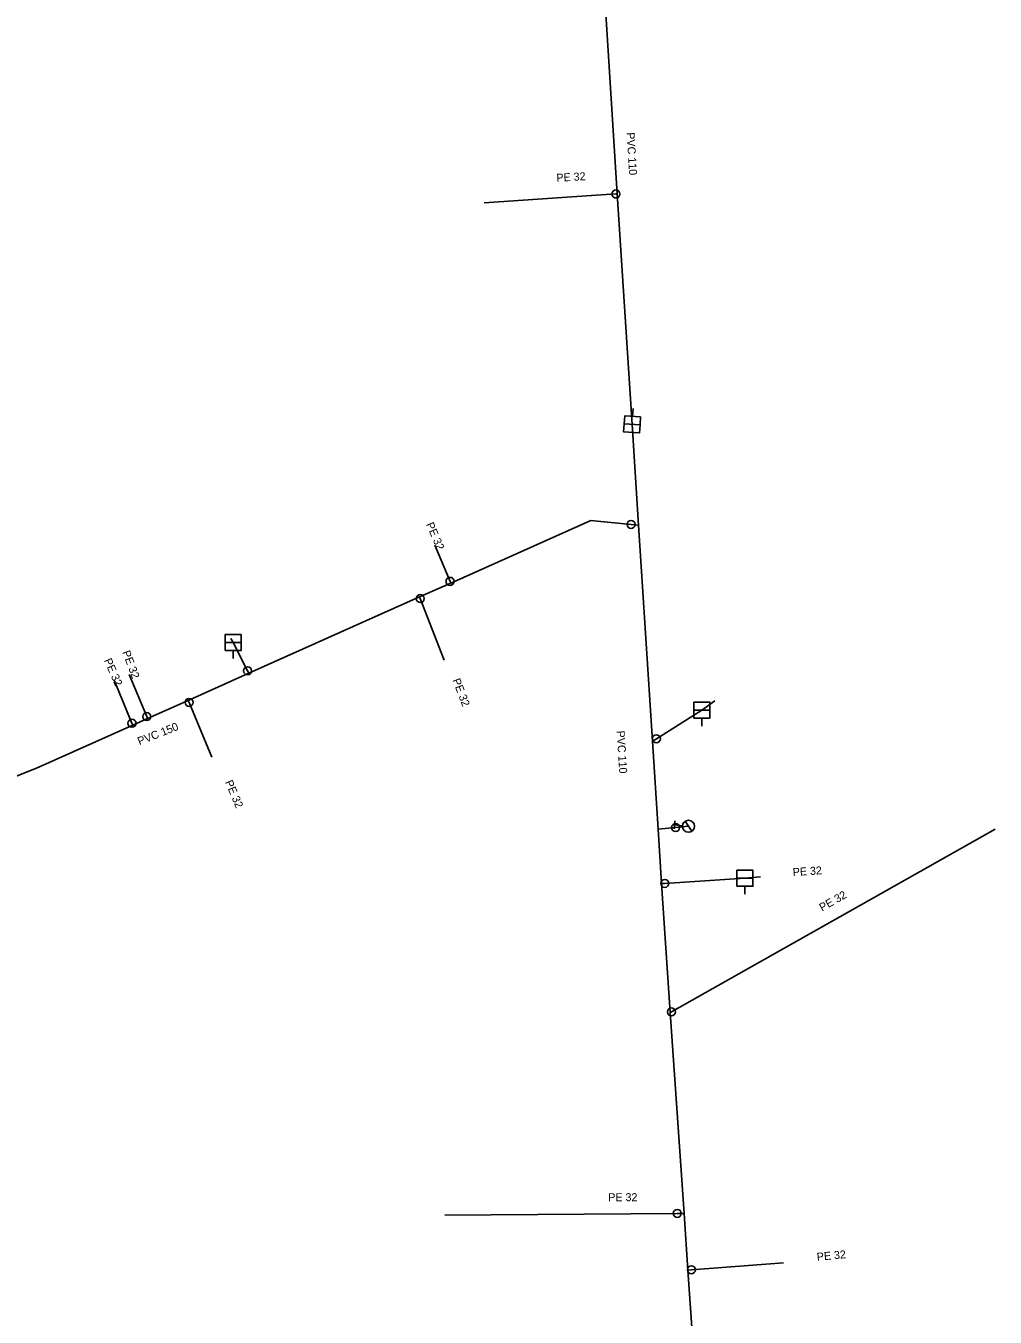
# Model space of a CAD drawing. Extents: x -725126 to -724740, y -1049524 to -1048684.
# Drawn here: x -724993.9 to -724872.7, y -1049098.7 to -1048937.4 of the extents above; entities that cross this region are included whole.
import ezdxf

# ---------------------------------------------------------------- set-up
doc = ezdxf.new("R2010")
doc.units = 0
doc.layers.add('Level 0', color=7, linetype='Continuous')

msp = doc.modelspace()

# ---------------------------------------------------------------- linework, layer by layer
at = {"layer": 'Level 0'}
for p, q in [((-724921.5, -1048934.52), (-724919.97, -1048958.36)), ((-724936.63, -1048959.48), (-724920.14, -1048958.37)), ((-724920.14, -1048958.37), (-724919.97, -1048958.36)), ((-724919.97, -1048958.36), (-724918.12, -1048987.16)), ((-724917.99, -1048985.16), (-724918.06, -1048986.16)), ((-724918.12, -1048987.16), (-724917.32, -1048999.76)), ((-724923.28, -1048999.16), (-724940.79, -1049006.98)), ((-724918.25, -1048999.66), (-724923.28, -1048999.16)), ((-724917.3, -1048999.75), (-724918.25, -1048999.66)), ((-724917.32, -1048999.76), (-724917.3, -1048999.75)), ((-724917.32, -1048999.76), (-724915.59, -1049026.75)), ((-724942.79, -1049002.23), (-724940.88, -1049006.77)), ((-724940.79, -1049006.98), (-724944.68, -1049008.72)), ((-724940.88, -1049006.77), (-724940.79, -1049006.98)), ((-724944.68, -1049008.72), (-724966.04, -1049018.25)), ((-724944.6, -1049008.93), (-724944.68, -1049008.72)), ((-724941.63, -1049016.62), (-724944.6, -1049008.93)), ((-724968.26, -1049013.9), (-724967.99, -1049014.42)), ((-724967.99, -1049014.42), (-724966.19, -1049017.95)), ((-724967.99, -1049016.42), (-724967.99, -1049015.42)), ((-724966.19, -1049017.95), (-724966.04, -1049018.25)), ((-724982.86, -1049019.12), (-724980.63, -1049024.5)), ((-724980.99, -1049018.4), (-724978.79, -1049023.67)), ((-724966.04, -1049018.25), (-724973.61, -1049021.64)), ((-724973.61, -1049021.64), (-724978.7, -1049023.91)), ((-724973.5, -1049021.9), (-724973.61, -1049021.64)), ((-724970.64, -1049028.72), (-724973.5, -1049021.9)), ((-724909.4, -1049022.86), (-724915.09, -1049026.44)), ((-724907.79, -1049021.68), (-724909.4, -1049022.86)), ((-724978.7, -1049023.91), (-724980.53, -1049024.73)), ((-724978.79, -1049023.67), (-724978.7, -1049023.91)), ((-724909.4, -1049024.86), (-724909.4, -1049023.86)), ((-724980.53, -1049024.73), (-724992.57, -1049030.1)), ((-724980.63, -1049024.5), (-724980.53, -1049024.73)), ((-724915.09, -1049026.44), (-724915.59, -1049026.75)), ((-724915.59, -1049026.75), (-724914.88, -1049037.75)), ((-724992.57, -1049030.1), (-724996.03, -1049031.47)), ((-724912.86, -1049037.69), (-724912.76, -1049036.7)), ((-724911.82, -1049037.3), (-724912.81, -1049037.2)), ((-724912.68, -1049037.53), (-724911.07, -1049037.37)), ((-724910.67, -1049038), (-724911.47, -1049036.74)), ((-724914.88, -1049037.75), (-724912.68, -1049037.53)), ((-724914.88, -1049037.75), (-724914.45, -1049044.53)), ((-724872.74, -1049037.73), (-724913.21, -1049060.57)), ((-724902.07, -1049043.7), (-724904.01, -1049043.86)), ((-724914.03, -1049044.51), (-724914.45, -1049044.53)), ((-724914.45, -1049044.53), (-724913.35, -1049060.65)), ((-724904.01, -1049043.86), (-724914.03, -1049044.51)), ((-724904.01, -1049045.86), (-724904.01, -1049044.86)), ((-724913.21, -1049060.57), (-724913.35, -1049060.65)), ((-724913.35, -1049060.65), (-724911.63, -1049085.74)), ((-724941.54, -1049085.95), (-724912.47, -1049085.74)), ((-724912.47, -1049085.74), (-724911.63, -1049085.74)), ((-724911.63, -1049085.74), (-724911.14, -1049092.83)), ((-724899.18, -1049091.93), (-724910.71, -1049092.79)), ((-724910.71, -1049092.79), (-724911.14, -1049092.83)), ((-724911.14, -1049092.83), (-724909.72, -1049113.49))]:
    msp.add_line(p, q, dxfattribs=at)
for points in [[(-724917.12, -1048987.22), (-724917.19, -1048988.22), (-724919.18, -1048988.09), (-724919.12, -1048987.1)], [(-724968.99, -1049014.42), (-724968.99, -1049013.42), (-724966.99, -1049013.42), (-724966.99, -1049014.42)], [(-724910.4, -1049022.86), (-724910.4, -1049021.86), (-724908.4, -1049021.86), (-724908.4, -1049022.86)], [(-724905.01, -1049043.86), (-724905.01, -1049042.86), (-724903.01, -1049042.86), (-724903.01, -1049043.86)]]:
    msp.add_lwpolyline(points, dxfattribs=at)
for points in [[(-724917.06, -1048986.23), (-724919.05, -1048986.1), (-724919.12, -1048987.1), (-724917.12, -1048987.22)], [(-724968.99, -1049015.42), (-724966.99, -1049015.42), (-724966.99, -1049014.42), (-724968.99, -1049014.42)], [(-724910.4, -1049023.86), (-724908.4, -1049023.86), (-724908.4, -1049022.86), (-724910.4, -1049022.86)], [(-724905.01, -1049044.86), (-724903.01, -1049044.86), (-724903.01, -1049043.86), (-724905.01, -1049043.86)]]:
    msp.add_lwpolyline(points, close=True, dxfattribs=at)
for centre, radius in [((-724920.14, -1048958.37), 0.5), ((-724918.25, -1048999.66), 0.5), ((-724940.88, -1049006.77), 0.5), ((-724944.6, -1049008.93), 0.5), ((-724966.19, -1049017.95), 0.5), ((-724973.5, -1049021.9), 0.5), ((-724980.63, -1049024.5), 0.5), ((-724978.79, -1049023.67), 0.5), ((-724915.09, -1049026.44), 0.5), ((-724912.68, -1049037.53), 0.5), ((-724911.07, -1049037.37), 0.75), ((-724914.03, -1049044.51), 0.5), ((-724913.21, -1049060.57), 0.5), ((-724912.47, -1049085.74), 0.5), ((-724910.71, -1049092.79), 0.5)]:
    msp.add_circle(centre, radius, dxfattribs=at)

# ---------------------------------------------------------------- texts
for s, rotation, p in [('PVC 110', 273.633, (-724918.82, -1048950.7)), ('PE 32', 3.366, (-724927.55, -1048956.85)), ('PE 32', 293.199, (-724943.89, -1048999.64)), ('PE 32', 293.499, (-724984.15, -1049016.64)), ('PE 32', 290.556, (-724981.86, -1049015.62)), ('PE 32', 290.854, (-724940.59, -1049019.11)), ('PVC 150', 21.601, (-724979.7, -1049027.26)), ('PVC 110', 273.693, (-724920.06, -1049025.46)), ('PE 32', 292.932, (-724969.02, -1049031.85)), ('PE 32', 3.712, (-724898.01, -1049043.6)), ('PE 32', 29.745, (-724894.37, -1049048.04)), ('PE 32', 5.315, (-724894.99, -1049091.67))]:
    msp.add_text(s, height=1, rotation=rotation, dxfattribs=at).set_placement(p)
msp.add_text('PE 32', height=1, dxfattribs=at).set_placement((-724921.1, -1049084.22))

doc.saveas('drawing.dxf')
